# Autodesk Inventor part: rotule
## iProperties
Shininess: 100.0
Length Units: 11269
Angle Units: 11279
Time Units: 11290
Mass Units: 11283
Length Display Precision: 3
Angle Display Precision: 2
Created: 2002-06
Part Number: rotule
Material: Par défaut
Document SubType Name: Modélisation
Designer: REVEST Pierre
Density: 0.0
Volumn: 0.0
Area: 0.0
PropertySet Name: Model Information
Control State: 0
Master: False
Checked Out: False
Author: REVEST Pierre
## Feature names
1. Révolution1 [Revolution]
2. Chanfrein1 [Chamfer]
3. Extrusion3
4. Congé2 [Fillet]
5. Extrusion4
6. Congé3 [Fillet]
7. Révolution2 [Revolution]
